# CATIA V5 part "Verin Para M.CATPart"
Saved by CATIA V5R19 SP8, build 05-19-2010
Part number: Verin Para M
Bounding box of the stored display mesh (mm): x -34.99 to 34.99, y -137.916 to 250.649, z -719.498 to -502.711
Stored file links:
  G:\EU_thinkMotion\CFAO_2010\MMS_groupe3\MMS_groupe3\rdalborgo\rdalborgo\Verin Para M.CATPart
  G:\EU_thinkMotion\CFAO_2010\MMS_groupe3\MMS_groupe3\rdalborgo\rdalborgo\rdalborgo.CATProduct
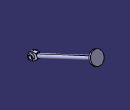
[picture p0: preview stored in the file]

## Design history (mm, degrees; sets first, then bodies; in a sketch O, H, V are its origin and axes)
Set1
  Plane1: linked copy from another document
  Point1 "B verin para": linked copy from another document
  Line1: linked copy from another document
  Point2: linked copy from another document
Body1 (main body)
  Sketch1 on Plane1, origin (0, 0, 0), H (0, 1, 0), V (0, 0, 1)
    point P1 (-117.9948, -699.5676)
    circle A1 centre (-117.9948, -699.5676) radius 10
    point P2 (-117.9948, -699.5676)
    reference projected point E1 (-117.9948, -699.5676) from Point1
    point P3 (-96.101, -675.5486)
    line L1 (-96.101, -675.5486) -> (-85.5236, -698.2007)
    line L2 (-85.5236, -698.2007) -> (-105.035, -714.8005)
    line L3 (-96.101, -675.5486) -> (-121.3544, -679.8518)
    reference projected line E2 (-123.6383, -702.2028) -> (466.1693, -426.7903) from Line1
    reference projected line E3 (-123.6383, -702.2028) -> (466.1693, -426.7903) from Line1
    reference projected point E4 (-117.9948, -699.5676) from Point1
    arc A2 centre (-117.9948, -699.5676) radius 20 from (-121.3544, -679.8518) to (-105.035, -714.8005) ccw
    radius A1 = 10
    length L1 = 25
    distance P3 E2 = 12.5
    distance L1 E4 = 30
    radius A2 = 20
    length L2 = 25.6174
    length L3 = 25.6174
    coincidence: P2 P1, P2 E1
    perpendicularity: L1 E3
  Pad1: profile Sketch1, direction (1, 0, 0), length 10, mirrored extent
  Sketch2 on Plane1, origin (0, 0, 0), H (0, 1, 0), V (0, 0, 1)
    circle A1 centre (-117.9948, -699.5676) radius 10
    point P1 (-117.9948, -699.5676)
    circle A2 centre (-117.9948, -699.5676) radius 15
    point P2 (-117.9948, -699.5676)
    reference projected point E1 (-117.9948, -699.5676) from Point1
    radius A1 = 10
    radius A2 = 15
    coincidence: P1 P2, P2 E1
  Pad2: profile Sketch2, direction (1, 0, 0), length 20, mirrored extent
  Sketch3 on Plane1, origin (0, 0, 0), H (0, 1, 0), V (0, 0, 1)
    point P1 (-99.8731, -691.1056)
    line L1 (-99.8731, -691.1056) -> (235.8897, -534.3201)
    point P2 (235.8897, -534.3201)
    line L2 (235.8897, -534.3201) -> (221.0813, -502.6071)
    line L3 (221.0813, -502.6071) -> (212.0204, -506.8381)
    line L4 (212.0204, -506.8381) -> (222.5979, -529.4902)
    line L5 (222.5979, -529.4902) -> (-104.1041, -682.0448)
    line L6 (-104.1041, -682.0448) -> (-99.8731, -691.1056)
    reference projected point E1 (235.8897, -534.3201) from Point2
    reference projected point E2 (-117.9948, -699.5676) from Point1
    reference projected line E3 (-123.6383, -702.2028) -> (466.1693, -426.7903) from Line1
    distance L5 L1 = 10
    distance L4 L2 = 10
    distance L3 L5 = 25
    distance P1 E2 = 20
    perpendicularity: L6 L5, L6 L1, L2 L1, L3 L2, L4 L5
    coincidence: P2 E1, P1 E3
  Shaft1: profile Sketch3, axis Line1, angle 360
